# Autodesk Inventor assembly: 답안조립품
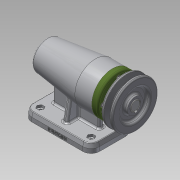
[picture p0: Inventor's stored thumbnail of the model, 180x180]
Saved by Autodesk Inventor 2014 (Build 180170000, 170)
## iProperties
Created: 2017-01
Part Number: 답안조립품
Document SubType Name: Assembly
Designer: Administrator
Author: Administrator
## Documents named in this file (12)
- C:\Users\Administrator\Desktop\470108V1004\답안조립품.iam
- C:\Users\Administrator\Desktop\470108V1004\본체.ipt
- C:\Users\Administrator\Desktop\470108V1004\V벨트풀리.ipt
- C:\Users\Administrator\Desktop\470108V1004\멈춤나사 M3x8.ipt
- C:\Users\Administrator\Desktop\470108V1004\베어링 6004.ipt
- C:\Users\Administrator\Desktop\470108V1004\베어링 51202.ipt
- C:\Users\Administrator\Desktop\470108V1004\볼트 M4 x 12.ipt
- C:\Users\Administrator\Desktop\470108V1004\어댑터슬리브.ipt
- C:\Users\Administrator\Desktop\470108V1004\오일 실.ipt
- C:\Users\Administrator\Desktop\470108V1004\축.ipt
- C:\Users\Administrator\Desktop\470108V1004\커버.ipt
- C:\Users\Administrator\Desktop\470108V1004\키 5 x 5 x 16.ipt
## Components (6 placed, 2 different names)
1. V벨트풀리:1 — 각도:2
2. ISO 4762 M4 x 12:1
3. ISO 4762 M4 x 12:2
4. ISO 4762 M4 x 12:3
5. ISO 4762 M4 x 12:4
6. ISO 4762 M4 x 12:5
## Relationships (1: Angle 1)
- 각도:2 [Angle]: V벨트풀리:1
